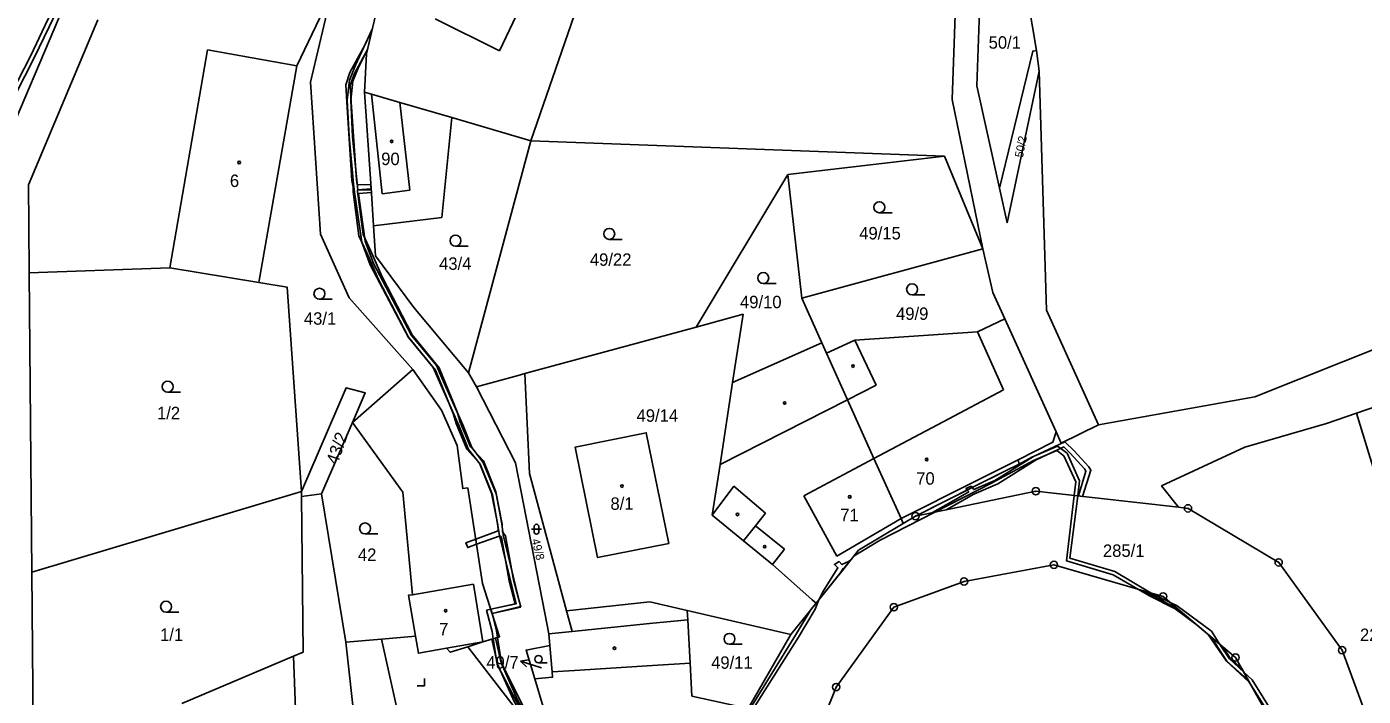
# Model space of a CAD drawing. Extents: x -779723 to -777378, y -1011169 to -1009297.
# Drawn here: x -779128.1 to -778945.2, y -1010207.4 to -1010115.8 of the extents above; entities that cross this region are included whole.
import ezdxf

# ---------------------------------------------------------------- set-up
doc = ezdxf.new("R2010")
doc.units = 0
for name, color, linetype in [('Hranice parcel', 7, 'Continuous'), ('Parcelní čísla', 7, 'Continuous'), ('Pop  PČ popisy', 7, 'Continuous'), ('Vnitřní kresba', 7, 'Continuous'), ('Věcná břemena k části', 7, 'Continuous'), ('Značky bodu BP', 7, 'Continuous'), ('Značky budov', 7, 'Continuous'), ('Značky kultur', 7, 'Continuous')]:
    doc.layers.add(name, color=color, linetype=linetype)

msp = doc.modelspace()

# ---------------------------------------------------------------- linework, layer by layer
at = {"layer": 'Hranice parcel'}
for p, q in [((-779059.16, -1010131.37), (-779049.6, -1010103.69)), ((-779134.25, -1010139.27), (-779120.37, -1010106.68)), ((-778989.56, -1010121.87), (-778989.92, -1010119.02)), ((-779069.96, -1010128.21), (-779059.16, -1010131.37)), ((-779067.67, -1010163.14), (-779059.16, -1010131.37)), ((-779059.16, -1010131.37), (-779002.53, -1010133.47)), ((-779002.53, -1010133.47), (-779023.96, -1010136)), ((-779002.53, -1010133.47), (-778997.25, -1010146.17)), ((-779023.96, -1010136), (-779036.53, -1010156.87)), ((-779022.06, -1010152.93), (-779023.96, -1010136)), ((-778997.25, -1010146.17), (-779022.06, -1010152.93)), ((-779127.81, -1010149.44), (-779127.44, -1010190.39)), ((-779022.06, -1010152.93), (-779019.31, -1010159.04)), ((-779036.53, -1010156.87), (-779059.96, -1010163.24)), ((-778987.25, -1010171.2), (-778994.26, -1010155.74)), ((-779019.31, -1010159.04), (-779031.52, -1010164.45)), ((-779018.68, -1010160.43), (-779019.31, -1010159.04)), ((-779075.29, -1010162.7), (-779083.57, -1010169.95)), ((-779067.67, -1010163.14), (-779066.59, -1010165.05)), ((-779083.57, -1010169.95), (-779087.81, -1010179.7)), ((-779090.53, -1010179.36), (-779127.44, -1010190.39)), ((-779090.52, -1010180.07), (-779090.53, -1010179.36)), ((-779087.81, -1010179.7), (-779090.52, -1010180.07)), ((-779084.45, -1010200.01), (-779087.81, -1010179.7)), ((-779008.17, -1010183.75), (-779006.48, -1010182.74)), ((-779127.44, -1010190.39), (-779127.2, -1010217)), ((-779023.53, -1010198.94), (-779020.09, -1010194.66)), ((-779023.53, -1010198.94), (-779037.72, -1010195.64)), ((-779079.59, -1010199.58), (-779074.93, -1010199.16)), ((-779056.69, -1010198.83), (-779056.55, -1010200.46)), ((-779029.4, -1010209.06), (-779023.53, -1010198.94)), ((-779079.59, -1010199.58), (-779084.45, -1010200.01)), ((-779081.11, -1010229.82), (-779084.45, -1010200.01)), ((-779106.91, -1010208.39), (-779091.64, -1010201.91)), ((-779089.99, -1010242.37), (-779091.64, -1010201.91))]:
    msp.add_line(p, q, dxfattribs=at)
for points in [[(-778981.44, -1010170.24), (-778960.05, -1010166.44), (-778917.58, -1010149.52), (-778869.36, -1010132.88), (-778766.08, -1010103.5), (-778721.06, -1010087.16), (-778695.97, -1010079.62), (-778608.15, -1010047.05)], [(-778997.25, -1010146.17), (-779001.45, -1010125.72), (-779000.52, -1010098.75), (-778997.81, -1010070.84), (-778997.31, -1010064.07)], [(-778994.71, -1010081.37), (-778997.43, -1010104.66), (-778998.08, -1010123.85), (-778994.99, -1010137.88)], [(-778989.92, -1010119.02), (-778992.7, -1010102.54), (-778994.71, -1010081.37)], [(-779069.85, -1010093.6), (-779079.37, -1010109.72), (-779081.62, -1010119.49), (-779081.9, -1010124.73)], [(-779096.36, -1010150.77), (-779091.18, -1010121.13), (-779086.41, -1010111.17)], [(-779075.29, -1010162.7), (-779083.99, -1010152.87), (-779087.92, -1010144.17), (-779089.32, -1010123.35), (-779086.41, -1010111.17)], [(-779118.39, -1010114.83), (-779127.92, -1010137.41), (-779127.87, -1010142.99), (-779127.81, -1010149.44)], [(-778994.99, -1010137.88), (-778990.45, -1010119.1), (-778989.92, -1010119.02)], [(-778994.99, -1010137.88), (-778993.95, -1010142.6), (-778989.56, -1010121.87)], [(-778989.56, -1010121.87), (-778988.54, -1010154.56), (-778981.44, -1010170.24)], [(-779081.9, -1010124.73), (-779080.97, -1010125), (-779077.09, -1010126.13), (-779069.96, -1010128.21)], [(-779081.9, -1010124.73), (-779080.96, -1010138.56), (-779080.66, -1010143.03)], [(-779080.66, -1010143.03), (-779071.34, -1010141.88), (-779069.96, -1010128.21)], [(-778847.96, -1010134.1), (-778870.96, -1010140.49), (-778896.72, -1010149.28), (-778930.42, -1010163.26), (-778946.12, -1010168.67)], [(-779080.66, -1010143.03), (-779080.38, -1010147.12), (-779075.16, -1010154.2), (-779067.67, -1010163.14)], [(-778994.26, -1010155.74), (-778995.89, -1010152.14), (-778997.25, -1010146.17)], [(-779127.81, -1010149.44), (-779108.53, -1010148.76), (-779096.36, -1010150.77)], [(-779090.53, -1010179.36), (-779092.51, -1010151.41), (-779096.36, -1010150.77)], [(-779036.53, -1010156.87), (-779030.09, -1010155.12), (-779031.52, -1010164.45)], [(-778994.26, -1010155.74), (-778998.02, -1010157.51), (-779014.8, -1010158.67), (-779018.68, -1010160.43)], [(-779018.68, -1010160.43), (-779015.8, -1010166.81), (-779012.17, -1010174.86), (-779008.46, -1010183.09), (-779008.17, -1010183.75)], [(-779067.78, -1010200.61), (-779065.7, -1010199.95), (-779063.41, -1010199.24), (-779065.75, -1010191.98), (-779067.77, -1010178.88), (-779068.46, -1010178.97), (-779069.24, -1010173.07), (-779071.35, -1010168.24), (-779075.29, -1010162.7)], [(-779059.96, -1010163.24), (-779060.89, -1010163.49), (-779066.59, -1010165.05)], [(-779054.24, -1010195.71), (-779059.34, -1010176.89), (-779059.96, -1010163.24)], [(-779031.52, -1010164.45), (-779033.24, -1010175.69), (-779034.3, -1010182.59), (-779030.01, -1010186.12), (-779026.06, -1010189.37), (-779020.62, -1010194.19), (-779020.09, -1010194.66)], [(-779090.53, -1010179.36), (-779084.42, -1010165.17), (-779081.81, -1010165.89), (-779083.57, -1010169.95)], [(-779066.59, -1010165.05), (-779061.23, -1010175.43), (-779057.23, -1010196.04), (-779056.69, -1010198.83)], [(-779083.57, -1010169.95), (-779076.68, -1010179.47), (-779075.35, -1010193.49), (-779075.89, -1010193.58), (-779074.93, -1010199.16)], [(-778946.12, -1010168.67), (-778950.22, -1010170.08), (-778961.42, -1010173.29), (-778972.81, -1010178.62), (-778970.48, -1010181.53)], [(-778883.82, -1010215.5), (-778932.35, -1010213.67), (-778946.12, -1010168.67)], [(-779040.25, -1010186.48), (-779050, -1010188.42), (-779053.06, -1010173.29), (-779043.34, -1010171.33), (-779040.25, -1010186.48)], [(-779006.48, -1010182.74), (-778998.36, -1010178.66), (-778994.25, -1010176.59), (-778992.32, -1010175.62), (-778992.44, -1010175.02), (-778987.68, -1010172.63), (-778987.25, -1010171.2)], [(-778987.25, -1010171.2), (-778986.55, -1010172.74), (-778981.44, -1010170.24)], [(-779091.64, -1010201.91), (-779090.29, -1010201.34), (-779090.52, -1010180.07)], [(-778970.48, -1010181.53), (-778987.62, -1010179.6), (-778990.02, -1010179.33), (-779006.48, -1010182.74)], [(-778970.48, -1010181.53), (-778969.19, -1010181.68), (-778956.78, -1010189.07), (-778948.1, -1010201.08), (-778944.59, -1010210.6), (-778941.69, -1010231.16)], [(-779020.09, -1010194.66), (-779016.32, -1010189.95), (-779014.29, -1010187.42), (-779008.17, -1010183.75)], [(-778951.52, -1010304.9), (-778950.58, -1010287.37), (-778950.58, -1010286.9), (-778950.34, -1010251.89), (-778953.35, -1010232.46), (-778955.45, -1010215), (-778962.68, -1010202.09), (-778972.6, -1010193.75), (-778987.54, -1010189.4), (-778999.84, -1010191.68), (-779009.45, -1010195.21), (-779017.34, -1010206.13), (-779023.92, -1010222.47), (-779024.96, -1010244.9), (-779026.78, -1010253.95)], [(-779037.72, -1010195.64), (-779042.86, -1010194.45), (-779054.24, -1010195.71)], [(-779054.24, -1010195.71), (-779053.48, -1010198.51), (-779056.69, -1010198.83)], [(-779029.4, -1010209.06), (-779037.09, -1010207.36), (-779037.33, -1010202.84), (-779037.65, -1010196.93), (-779037.72, -1010195.64)], [(-779074.93, -1010199.16), (-779074.53, -1010201.5), (-779070.67, -1010200.83), (-779070.18, -1010201.36), (-779067.78, -1010200.61)], [(-779076.2, -1010214.76), (-779078.76, -1010203.29), (-779079.59, -1010199.58)], [(-779067.78, -1010200.61), (-779062.19, -1010207.85), (-779059.7, -1010211.07)], [(-779056.55, -1010200.46), (-779059.79, -1010201.08), (-779058.6, -1010204.99)], [(-779056.55, -1010200.46), (-779056.24, -1010204.04), (-779056.17, -1010204.79), (-779058.6, -1010204.99)], [(-779058.6, -1010204.99), (-779057.43, -1010208.85), (-779056.71, -1010211.24), (-779055.26, -1010212.45), (-779047.2, -1010219.18), (-779045.87, -1010220.45), (-779039.55, -1010226.53), (-779034.42, -1010230.71)]]:
    msp.add_lwpolyline(points, dxfattribs=at)
at = {"layer": 'Pop  PČ popisy'}
for p, q in [((-779060.56, -1010202.6), (-779059.46, -1010202.42)), ((-779057.69, -1010203.48), (-779060.56, -1010202.6)), ((-779060.56, -1010202.6), (-779059.75, -1010203.37)), ((-779057.66, -1010203.49), (-779057.69, -1010203.48))]:
    msp.add_line(p, q, dxfattribs=at)
at = {"layer": 'Vnitřní kresba'}
for p, q in [((-779072.23, -1010114.72), (-779063.43, -1010119.08)), ((-779060.71, -1010113.33), (-779063.43, -1010119.08)), ((-779108.53, -1010148.76), (-779103.38, -1010118.93)), ((-779103.38, -1010118.93), (-779091.18, -1010121.13)), ((-779080.97, -1010125), (-779079.51, -1010138.63)), ((-779077.09, -1010126.13), (-779075.69, -1010138.16)), ((-779079.51, -1010138.63), (-779075.69, -1010138.16)), ((-779011.87, -1010164.81), (-779014.8, -1010158.67)), ((-778998.02, -1010157.51), (-778994.45, -1010165.45)), ((-779015.8, -1010166.81), (-779011.87, -1010164.81)), ((-779002.7, -1010169.83), (-778994.45, -1010165.45)), ((-779033.24, -1010175.69), (-779015.8, -1010166.81)), ((-779012.17, -1010174.86), (-779002.7, -1010169.83)), ((-779021.79, -1010179.97), (-779012.17, -1010174.86)), ((-778992.44, -1010175.02), (-778994.55, -1010176.08)), ((-778994.55, -1010176.08), (-778998.62, -1010178.13)), ((-779034.3, -1010182.59), (-779031.34, -1010178.65)), ((-779031.34, -1010178.65), (-779027.03, -1010182.36)), ((-778998.62, -1010178.13), (-779008.46, -1010183.09)), ((-779017.26, -1010188.23), (-779021.79, -1010179.97)), ((-779027.03, -1010182.36), (-779028.4, -1010184.09)), ((-779028.4, -1010184.09), (-779030.01, -1010186.12)), ((-779028.4, -1010184.09), (-779024.42, -1010187.27)), ((-779008.46, -1010183.09), (-779017.26, -1010188.23)), ((-779026.06, -1010189.37), (-779024.42, -1010187.27)), ((-779075.35, -1010193.49), (-779066.99, -1010192.05)), ((-779066.99, -1010192.05), (-779065.7, -1010199.95)), ((-779042.9, -1010197.45), (-779037.65, -1010196.93)), ((-779053.48, -1010198.51), (-779042.9, -1010197.45)), ((-779065.7, -1010199.95), (-779070.67, -1010200.83)), ((-779042.47, -1010203.17), (-779037.33, -1010202.84)), ((-779056.24, -1010204.04), (-779053.16, -1010203.85)), ((-779053.16, -1010203.85), (-779042.47, -1010203.17))]:
    msp.add_line(p, q, dxfattribs=at)
at = {"layer": 'Věcná břemena k části'}
for points in [[(-779135.94, -1010139.37), (-779135.77, -1010138.23), (-779135.57, -1010137.43), (-779133.58, -1010132.88), (-779129.66, -1010125.05), (-779127.1, -1010120.05), (-779125.06, -1010115.81), (-779123.42, -1010112.45), (-779122.91, -1010110.97), (-779121.16, -1010108.46), (-779121.06, -1010108.3), (-779120.37, -1010106.68), (-779117.94, -1010102.23), (-779119.71, -1010105.03), (-779121.66, -1010108.12), (-779123.45, -1010110.69), (-779123.98, -1010112.21), (-779125.6, -1010115.55), (-779127.64, -1010119.79), (-779130.2, -1010124.77), (-779134.12, -1010132.62), (-779136.15, -1010137.23), (-779136.35, -1010138.11), (-779136.54, -1010139.4)], [(-779060.53, -1010195.2), (-779061.51, -1010191.46), (-779062.6, -1010185.42), (-779063, -1010184.91), (-779063.06, -1010183.86), (-779063.95, -1010179.42), (-779065.63, -1010175.19), (-779067.38, -1010173.27), (-779068.81, -1010169.88), (-779069.22, -1010168.48), (-779071.68, -1010162.43), (-779075.37, -1010157.93), (-779079.46, -1010150.11), (-779081.04, -1010146.48), (-779082.11, -1010144.21), (-779082.85, -1010138.33), (-779082.85, -1010138.08), (-779080.99, -1010138.13), (-779081.04, -1010137.43), (-779082.91, -1010137.38), (-779083.02, -1010136.72), (-779083.72, -1010126.08), (-779083.86, -1010123.82), (-779083.34, -1010122.29), (-779081.48, -1010118.88), (-779080.84, -1010116.11), (-779081.8, -1010118.22), (-779083.9, -1010122.05), (-779084.46, -1010123.74), (-779084.32, -1010126.12), (-779083.62, -1010136.8), (-779083.45, -1010137.75), (-779083.45, -1010138.37), (-779082.69, -1010144.37), (-779081.58, -1010146.72), (-779080, -1010150.37), (-779075.87, -1010158.27), (-779072.2, -1010162.75), (-779069.78, -1010168.68), (-779069.37, -1010170.08), (-779067.9, -1010173.59), (-779066.15, -1010175.51), (-779064.53, -1010179.6), (-779063.66, -1010183.94), (-779063.61, -1010184.76), (-779066.69, -1010185.89), (-779066.58, -1010186.6), (-779063.36, -1010185.42), (-779063.16, -1010185.68), (-779062.09, -1010191.58), (-779061.27, -1010194.74), (-779064.63, -1010195.47), (-779064.44, -1010196.05)], [(-779064.44, -1010196.05), (-779060.54, -1010195.12), (-779062.94, -1010185.3), (-779063.13, -1010183.8), (-779063.89, -1010179.67), (-779065.65, -1010175.39), (-779067.22, -1010173.37), (-779068.47, -1010170.23), (-779071.01, -1010164.56), (-779072.05, -1010162.15), (-779075.48, -1010158.02), (-779080.67, -1010148.16), (-779081.8, -1010145.12), (-779082.73, -1010138.59), (-779080.97, -1010138.45), (-779081, -1010137.96), (-779082.81, -1010138.09), (-779082.93, -1010137.22), (-779083.53, -1010130.79), (-779083.76, -1010125.85), (-779083.49, -1010123.21), (-779082.66, -1010121.24), (-779081.48, -1010118.88), (-779080.84, -1010116.11), (-779083.12, -1010121.04), (-779083.97, -1010123.09), (-779084.26, -1010125.83), (-779084.02, -1010130.82), (-779083.43, -1010137.28), (-779083.27, -1010138.4), (-779082.28, -1010145.24), (-779081.13, -1010148.36), (-779075.9, -1010158.3), (-779072.49, -1010162.41), (-779071.46, -1010164.76), (-779068.93, -1010170.42), (-779067.66, -1010173.63), (-779066.09, -1010175.65), (-779064.37, -1010179.81), (-779063.44, -1010185.4), (-779061.14, -1010194.74), (-779064.63, -1010195.47)], [(-779006.48, -1010182.74), (-779003.86, -1010182.2), (-778996.07, -1010178.21), (-778990.34, -1010175.15), (-778987.14, -1010173.78), (-778986.19, -1010174.49), (-778984.55, -1010178.04), (-778984.77, -1010179.92), (-778984.28, -1010179.98), (-778984.02, -1010177.93), (-778985.75, -1010174.15), (-778987.05, -1010173.15), (-778990.58, -1010174.67), (-778992.32, -1010175.62), (-778994.25, -1010176.59), (-778996.15, -1010177.55), (-778996.64, -1010177.79)], [(-778984.2, -1010179.98), (-778983.63, -1010180.05), (-778982.48, -1010176.47), (-778982.75, -1010176.02), (-778984.77, -1010173.79), (-778986.04, -1010172.58), (-778990.36, -1010174.6), (-778995.62, -1010177.86), (-778998.51, -1010179.1), (-778998.72, -1010178.84), (-778999.4, -1010179.18), (-778999.19, -1010179.44), (-779002.3, -1010181.2), (-779004.15, -1010182.26), (-779002.3, -1010181.87), (-779001.89, -1010181.64), (-778998.49, -1010179.72), (-778995.24, -1010178.31), (-778989.95, -1010175.05), (-778986.18, -1010173.28), (-778985.31, -1010174.11), (-778983.34, -1010176.29), (-778983.16, -1010176.6)], [(-778999.58, -1010178.95), (-778999.4, -1010179.18), (-778998.72, -1010178.84), (-778998.89, -1010178.64)], [(-778975.95, -1010192.78), (-778974.25, -1010193.27), (-778979.22, -1010190.32), (-778985.35, -1010188.5), (-778984.28, -1010179.98), (-778984.77, -1010179.92), (-778985.81, -1010188.88), (-778979.42, -1010190.78)], [(-779003.86, -1010182.2), (-779006.48, -1010182.74), (-779008.17, -1010183.75), (-779014.29, -1010187.42), (-779014.88, -1010188.16), (-779011.33, -1010186.02)], [(-779066.69, -1010185.89), (-779068.02, -1010186.38), (-779067.78, -1010187.04), (-779066.58, -1010186.6)], [(-779019.73, -1010194.2), (-779016.8, -1010190.55), (-779016.41, -1010189.93), (-779016.24, -1010189.85), (-779015.41, -1010188.81), (-779015.67, -1010188.97), (-779016.55, -1010189.36), (-779016.95, -1010188.96), (-779017.59, -1010189.35), (-779017.11, -1010189.81), (-779019.05, -1010192.89)], [(-778970.94, -1010195.42), (-778968.1, -1010197.53), (-778971.7, -1010194.5), (-778974.25, -1010193.27), (-778975.95, -1010192.78), (-778974.46, -1010193.63)], [(-778971.01, -1010195.26), (-778969.26, -1010196.56), (-778972.6, -1010193.75), (-778975.18, -1010193)], [(-779063.71, -1010199.33), (-779063.85, -1010198.43), (-779064.44, -1010196.05), (-779064.63, -1010195.47), (-779065.2, -1010195.59), (-779064.43, -1010198.55), (-779064.28, -1010199.51)], [(-779030.46, -1010211.85), (-779022.51, -1010199.29), (-779020.23, -1010195.48), (-779019.73, -1010194.2), (-779020.75, -1010195.48), (-779022.93, -1010199.03), (-779029.85, -1010210.23)], [(-778964.82, -1010200.29), (-778965.99, -1010198.48), (-778970.68, -1010195), (-778971.7, -1010194.5), (-778968.1, -1010197.53), (-778966.45, -1010198.92)], [(-778960.8, -1010205.44), (-778961.57, -1010204.08), (-778963.53, -1010202.29), (-778964.82, -1010200.29), (-778966.45, -1010198.92), (-778963.91, -1010202.61)], [(-779057.92, -1010213.38), (-779060.97, -1010207.9), (-779063.22, -1010202.83), (-779063.98, -1010199.42), (-779064.47, -1010199.57), (-779063.7, -1010202.99), (-779061.41, -1010208.12), (-779059.7, -1010211.07)], [(-779051.34, -1010220.95), (-779052.56, -1010219.3), (-779054.19, -1010217.07), (-779057.26, -1010213.11), (-779060.05, -1010209.02), (-779063.16, -1010202.87), (-779063.71, -1010199.33), (-779064.28, -1010199.51), (-779063.74, -1010203.05), (-779060.51, -1010209.23), (-779057.68, -1010213.39), (-779054.6, -1010217.35), (-779053.53, -1010218.82)], [(-778961.1, -1010205.06), (-778960.64, -1010205.73), (-778961.84, -1010203.6), (-778963.42, -1010202.19), (-778964.42, -1010200.62), (-778965.96, -1010199.33), (-778963.88, -1010202.59)], [(-778957.38, -1010211.55), (-778955.96, -1010214.09), (-778957.39, -1010209.96), (-778960.42, -1010205.12), (-778961.57, -1010204.08), (-778960.8, -1010205.44), (-778957.85, -1010210.18)]]:
    msp.add_lwpolyline(points, close=True, dxfattribs=at)
at = {"layer": 'Značky bodu BP'}
for centre, radius in [((-778990.02, -1010179.33), 0.5), ((-778990.02, -1010179.33), 0.0303), ((-779006.48, -1010182.74), 0.5), ((-779006.48, -1010182.74), 0.0303), ((-778969.19, -1010181.68), 0.5), ((-778969.19, -1010181.68), 0.0303), ((-778987.54, -1010189.4), 0.5), ((-778987.54, -1010189.4), 0.0303), ((-778956.78, -1010189.07), 0.5), ((-778956.78, -1010189.07), 0.0303), ((-778999.84, -1010191.68), 0.5), ((-778999.84, -1010191.68), 0.0303), ((-778972.6, -1010193.75), 0.5), ((-778972.6, -1010193.75), 0.0303), ((-779009.45, -1010195.21), 0.5), ((-779009.45, -1010195.21), 0.0303), ((-778948.1, -1010201.08), 0.5), ((-778948.1, -1010201.08), 0.0303), ((-778962.68, -1010202.09), 0.5), ((-778962.68, -1010202.09), 0.0303), ((-779017.34, -1010206.13), 0.5), ((-779017.34, -1010206.13), 0.0303)]:
    msp.add_circle(centre, radius, dxfattribs=at)
at = {"layer": 'Značky budov'}
for centre in [(-779078.19, -1010131.47), (-779099.07, -1010134.35), (-779015.04, -1010162.21), (-779024.4, -1010167.26), (-779004.96, -1010175), (-779046.67, -1010178.63), (-779015.49, -1010180.1), (-779030.85, -1010182.51), (-779027.13, -1010186.92), (-779070.79, -1010195.69), (-779047.69, -1010200.82)]:
    msp.add_circle(centre, 0.175, dxfattribs=at)
at = {"layer": 'Značky kultur'}
for p, q in [((-779011.44, -1010141.23), (-779009.69, -1010141.23)), ((-779069.45, -1010145.8), (-779067.7, -1010145.8)), ((-779048.41, -1010144.87), (-779046.66, -1010144.87)), ((-779027.33, -1010150.91), (-779025.58, -1010150.91)), ((-779088.07, -1010153.07), (-779086.32, -1010153.07)), ((-779006.95, -1010152.46), (-779005.2, -1010152.46)), ((-779108.85, -1010165.78), (-779107.1, -1010165.78)), ((-779059.03, -1010184.53), (-779057.69, -1010184.53)), ((-779058.7, -1010184.2), (-779058.7, -1010184.87)), ((-779058.03, -1010184.87), (-779058.03, -1010184.2)), ((-779081.83, -1010185.18), (-779080.08, -1010185.18)), ((-779109.07, -1010195.88), (-779107.32, -1010195.88)), ((-779031.95, -1010200.28), (-779030.2, -1010200.28)), ((-779058.08, -1010202.81), (-779056.91, -1010202.81)), ((-779074.69, -1010205.95), (-779073.69, -1010205.95)), ((-779073.69, -1010205.95), (-779073.69, -1010204.95))]:
    msp.add_line(p, q, dxfattribs=at)
for centre, radius in [((-779011.44, -1010140.48), 0.75), ((-779069.45, -1010145.05), 0.75), ((-779048.41, -1010144.12), 0.75), ((-779027.33, -1010150.16), 0.75), ((-779088.07, -1010152.32), 0.75), ((-779006.95, -1010151.71), 0.75), ((-779108.85, -1010165.03), 0.75), ((-779081.83, -1010184.43), 0.75), ((-779109.07, -1010195.13), 0.75), ((-779031.95, -1010199.53), 0.75), ((-779058.09, -1010202.31), 0.502)]:
    msp.add_circle(centre, radius, dxfattribs=at)
for centre, start, end in [((-779058.36, -1010184.2), 0, 180), ((-779058.36, -1010184.87), 180, 359.9879)]:
    msp.add_arc(centre, 0.335, start, end, dxfattribs=at)

# ---------------------------------------------------------------- texts
at = {"layer": 'Parcelní čísla'}
for s, p in [('50/1', (-778996.48, -1010118.78)), ('90', (-779079.62, -1010134.71)), ('6', (-779100.33, -1010137.71)), ('49/15', (-779014.19, -1010144.88)), ('43/4', (-779071.7, -1010149.04)), ('49/22', (-779051.06, -1010148.49)), ('49/10', (-779030.51, -1010154.29)), ('43/1', (-779090.2, -1010156.55)), ('49/9', (-779009.15, -1010155.89)), ('1/2', (-779110.31, -1010169.48)), ('49/14', (-779044.67, -1010169.83)), ('70', (-779006.39, -1010178.44)), ('8/1', (-779048.24, -1010181.88)), ('71', (-779016.79, -1010183.44)), ('42', (-779082.81, -1010188.87)), ('285/1', (-778980.83, -1010188.32)), ('7', (-779071.69, -1010199.05)), ('1/1', (-779109.89, -1010199.81)), ('224/2', (-778945.65, -1010199.83)), ('49/7', (-779065.23, -1010203.6)), ('49/11', (-779034.46, -1010203.63))]:
    msp.add_text(s, height=1.7, dxfattribs=at).set_placement(p)
for s, height, rotation, p in [('50/2', 1.14, 79, (-778991.8, -1010133.76)), ('43/2', 1.7, 71, (-779085.6, -1010175.81)), ('49/8', 1.14, 284, (-779059.06, -1010185.98))]:
    msp.add_text(s, height=height, rotation=rotation, dxfattribs=at).set_placement(p)

doc.saveas('drawing.dxf')
